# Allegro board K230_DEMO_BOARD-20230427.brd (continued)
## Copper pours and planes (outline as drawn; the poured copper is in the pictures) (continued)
GND on TOP: 58.42,76.2 58.42,73.66 59.44,72.64 59.44,70.36 60.45,69.34 60.45,67.56 60.58,67.44 64.01,67.44 64.39,67.82 64.39,89.53 64.26,89.66 62.48,89.66 62.36,89.53 62.36,76.58 62.23,76.45 58.67,76.45
GND on TOP: 69.98,101.22 69.98,97.66 69.85,97.54 64.9,97.54 64.77,97.66 64.77,101.6 64.9,101.73 66.8,101.73 66.93,101.6 66.93,100.58 66.8,100.46 65.66,100.46 65.53,100.33 65.53,98.68 65.66,98.55 67.56,98.55 67.69,98.68 67.69,99.82 67.82,99.95 68.96,99.95 69.09,100.08 69.09,101.22 69.22,101.35 69.85,101.35
GND on TOP: 71.88,58.29 74.55,58.29 74.68,58.17 74.68,56.26 74.55,56.13 71.88,56.13 71.75,56.26 71.75,58.17
GND on TOP: 65.02,81.03 67.56,81.03 68.07,80.52 69.09,80.52 69.22,80.39 69.22,79.38 69.09,79.25 65.02,79.25 64.9,79.38 64.9,80.9
GND on TOP: outline of 158 points within 12.19,6.73 67.31,41.15 ; 2 cut-outs
GND on TOP: 51.05,93.09 50.93,93.22 50.93,96.01 51.05,96.14 53.85,96.14 53.98,96.27 53.98,98.17 54.48,98.68 54.48,100.84 54.36,100.97 53.72,100.97 53.59,101.09 53.59,101.98 53.72,102.11 56.26,102.11 56.39,101.98 56.39,100.97 56.26,100.84 55.63,100.84 55.5,100.71 55.5,98.42 56.01,97.92 56.01,96.27 56.13,96.14 57.53,96.14 57.66,96.01 57.66,93.47 57.53,93.34 52.32,93.34 52.07,93.09
GND on TOP: 57.03,104.8 56.9,104.92 56.9,112.03 57.03,112.16 64.27,112.16 64.4,112.03 64.4,104.92 64.27,104.8
GND on TOP: 53.47,43.56 53.34,43.69 53.34,45.34 52.96,45.72 52.96,48.77 52.2,49.53 51.56,49.53 51.44,49.66 51.44,50.16 51.31,50.29 49.15,50.29 49.02,50.42 49.02,51.94 49.15,52.07 50.04,52.07 50.16,51.94 50.16,51.44 50.29,51.31 53.34,51.31 53.47,51.44 53.47,62.48 53.59,62.61 54.99,62.61 55.12,62.74 55.12,64.64 55.24,64.77 58.55,64.77 58.67,64.64 58.67,51.31 58.93,51.05 61.98,51.05 62.36,51.44 62.48,51.44 62.61,51.31 62.61,47.24 62.23,46.86 62.23,44.96 60.83,43.56
GND on TOP: 41.15,72.14 42.55,72.14 43.05,71.63 45.21,71.63 45.34,71.5 45.34,68.83 45.09,68.58 43.81,68.58 41.02,71.37 41.02,72.01
GND on TOP: 15.62,53.72 15.49,53.59 12.19,53.59 12.06,53.72 12.06,57.15 12.19,57.28 15.49,57.28 15.62,57.15
GND on TOP: 51.82,78.99 51.82,77.72 51.94,77.6 53.72,77.6 53.85,77.72 53.85,79.76 53.72,79.88 52.32,79.88 52.2,80.01 52.2,81.53 52.07,81.66 50.04,81.66 49.91,81.79 49.91,82.3 50.04,82.42 54.48,82.42 54.74,82.17 54.74,76.96 54.61,76.83 50.16,76.83 50.04,76.96 50.04,78.87 50.29,79.12 51.69,79.12
GND on TOP: 71.88,70.36 74.68,70.36 74.8,70.23 74.8,68.45 74.68,68.33 71.88,68.33 71.75,68.45 71.75,70.23
GND on TOP: 4.32,84.84 4.19,84.96 4.19,87.5 4.32,87.63 5.84,87.63 7.11,86.36 7.11,84.96 6.99,84.84
GND on TOP: 71.88,66.17 74.42,66.17 74.55,66.04 74.55,64.26 74.42,64.14 71.88,64.14 71.75,64.26 71.75,66.04
GND on TOP: 50.93,76.33 52.96,76.33 53.09,76.2 53.09,72.9 52.96,72.77 52.45,72.77 52.32,72.9 52.32,74.68 52.2,74.8 50.93,74.8 50.8,74.93 50.8,76.2
GND on BOTTOM: 20.95,53.34 21.08,53.21 21.08,51.56 20.95,51.44 17.65,51.44 17.27,51.82 17.27,56.39 17.4,56.52 19.43,56.52 19.56,56.39 19.56,53.47 19.68,53.34
GND on BOTTOM: 62.87,13.97 63.25,14.35 67.69,14.35 67.94,14.1 67.94,11.68 67.82,11.56 55.5,11.56 55.24,11.81 55.24,13.84 55.37,13.97
GND on BOTTOM: 46.23,111.38 47.62,111.38 47.75,111.25 47.75,109.86 47.62,109.73 46.23,109.73 46.1,109.86 46.1,111.25
GND on BOTTOM: 73.66,89.28 75.56,89.28 75.69,89.15 75.69,85.98 75.56,85.85 73.66,85.85 73.53,85.98 73.53,89.15
GND on BOTTOM: 38.99,115.57 38.99,116.84 39.12,116.97 41.27,116.97 41.4,116.84 41.4,116.33 41.27,116.2 40.64,116.2 40.51,116.08 40.51,115.57 40.39,115.44 39.12,115.44
GND on BOTTOM: 57.54,111.53 57.67,111.65 63.76,111.65 63.89,111.53 63.89,105.43 63.76,105.3 57.67,105.3 57.54,105.43
GND on BOTTOM: 0.64,103.63 0.64,138 1.03,138.96 2,139.36 39.45,139.36 40.01,138.81 40.01,121.92 39.62,121.54 26.29,121.54 25.65,120.9 25.65,103.5 25.27,103.12 1.14,103.12
GND on GND02: 2,0.64 1.03,1.03 0.64,2 0.64,138 1.03,138.96 2,139.36 58.25,139.36 58.55,139.06 58.55,131.06 47.88,120.4 47.88,108.2 30.61,90.93 30.61,85.34 31.37,84.58 31.37,83.82 30.86,83.31 30.86,82.42 30.99,82.3 31.88,82.3 32.66,83.08 32.66,87.27 33.53,88.14 34.16,88.14 35.81,89.79 35.81,90.55 51.94,106.68 51.94,117.98 56.13,122.17 60.83,122.17 63.25,119.76 63.25,116.33 63.88,115.7 78.8,115.7 79.43,115.06 79.43,2 79.03,1.03 78.07,0.64
GND on ART03: 2,0.64 1.03,1.03 0.64,2 0.64,54.36 2.16,54.36 2.54,53.98 2.54,9.02 8.89,2.67 70.48,2.67 76.45,8.64 76.45,111.76 76.71,112.01 79.18,112.01 79.43,111.76 79.43,2 79.03,1.03 78.07,0.64
GND on ART03: 0.64,64.13 0.64,138 1.03,138.96 2,139.36 57.87,139.36 58.55,138.68 58.55,131.06 58.04,130.56 10.29,130.56 4.19,124.46 4.19,92.08 2.41,90.3 2.41,64.14 2.03,63.75 1.02,63.75
GND on POWER04: 2,0.64 1.03,1.03 0.64,2 0.64,53.47 1.27,54.1 2.03,54.1 3.05,53.09 3.05,13.21 3.93,12.33 3.96,12.25 3.91,12.17 3.8,10.78 5.19,10.9 5.26,10.94 5.34,10.91 7.62,8.64 34.04,8.64 34.29,8.38 34.29,1.14 33.78,0.64
GND on POWER04: 79.43,111.25 79.43,2 79.03,1.03 78.07,0.64 42.16,0.64 41.66,1.14 41.66,7.62 42.16,8.13 69.98,8.13 70.36,8.51 70.36,32.13 75.69,37.47 75.69,85.6 75.95,85.85 75.95,89.41 75.69,89.66 75.69,111.25 75.95,111.51 79.18,111.51
GND on POWER04: 1.14,71.75 0.64,72.26 0.64,78.36 0.64,79.88 0.64,138 1.03,138.96 2,139.36 57.91,139.36 58.42,138.86 58.42,134.61 58.17,134.36 58.17,134.37 5.59,134.37 4.06,132.84 4.06,116.36 1.64,114 4.06,111.64 4.06,78.3 3.53,77.49 4.04,76.65 4.04,75.75 3.53,74.84 4.2,74.05 4.19,74.04 4.19,72.14 3.81,71.75
GND on GND05: 2,0.64 1.03,1.03 0.64,2 0.64,138 1.03,138.96 2,139.36 58.55,139.36 58.55,124.46 63.25,119.76 63.25,116.33 63.88,115.7 78.8,115.7 79.43,115.06 79.43,2 79.03,1.03 78.07,0.64
GND on ART06: 71.88,1.27 71.88,18.92 73.79,20.83 73.79,38.23 72.64,39.37 72.64,44.2 75.06,46.61 75.06,108.84 73.28,110.62 73.28,115.06 73.91,115.7 78.93,115.7 79.43,115.19 79.43,2 79.03,1.03 78.07,0.64 72.52,0.64
GND on ART06: 0.64,86.87 0.64,138 1.03,138.96 2,139.36 25.91,139.36 26.23,139.05 26.23,135.83 6.73,116.33 6.73,104.78 4.95,103 4.95,87.63 4.19,86.87
GND on GND07: 2,0.64 1.03,1.03 0.64,2 0.64,138 1.03,138.96 2,139.36 58.55,139.36 58.55,124.46 63.25,119.76 63.25,116.33 63.88,115.7 78.74,115.7 79.43,115 79.43,2 79.03,1.03 78.07,0.64
GND_SIGNAL on TOP: 64.52,138.18 61.21,138.18 61.09,138.3 61.09,139.19 61.21,139.32 64.52,139.32 64.64,139.19 64.64,138.3
GND_SIGNAL on BOTTOM: 36.2,88.65 36.2,87.25 36.07,87.12 33.78,87.12 33.66,87.25 33.66,89.66 32.26,91.06 31.88,91.06 31.62,90.81 31.62,88.14 32.13,87.63 32.13,87.12 32,87 30.86,87 30.73,87.12 30.73,91.06 31.5,91.82 33.02,91.82
GND_SIGNAL on GND02: 63.88,120.65 61.72,122.81 56.01,122.81 51.44,118.24 51.44,106.81 35.43,90.81 35.43,89.92 34.04,88.52 33.4,88.52 32.51,87.63 32.51,83.19 31.75,82.42 31.11,82.42 30.99,82.55 30.99,83.31 31.5,83.82 31.5,84.84 30.73,85.6 30.73,90.55 48.39,108.2 48.39,120.02 59.56,131.19 59.56,139.11 59.82,139.36 78.07,139.36 79.03,138.96 79.43,138 79.43,116.97 78.93,116.46 64.14,116.46 63.88,116.71
GND_SIGNAL on ART03, POWER04, GND05, ART06, GND07: 63.88,120.65 59.56,124.97 59.56,139.06 59.86,139.36 78.07,139.36 79.03,138.96 79.43,138 79.43,116.97 78.93,116.46 64.14,116.46 63.88,116.71
VBUS on TOP: 73.03,11.18 69.47,11.18 69.22,11.43 69.22,16.26 69.72,16.76 73.15,16.76 73.28,16.64 73.28,16.26 73.15,16.13 71.25,16.13 71.12,16 71.12,11.94 71.25,11.81 73.03,11.81 73.15,11.68 73.15,11.3
VDD_1V8 on TOP: 27.3,30.86 27.43,30.99 28.45,30.99 28.57,30.86 28.57,25.65 28.45,25.53 27.43,25.53 27.3,25.65
VDD_1V8 on TOP: 15.62,47.37 15.62,43.69 15.49,43.56 14.61,43.56 14.48,43.69 14.48,47.37 14.61,47.5 15.49,47.5
VDD_1V8 on TOP: 22.23,29.21 22.35,29.34 22.35,30.73 22.48,30.86 23.24,30.86 23.37,30.73 23.37,25.65 23.24,25.53 22.35,25.53 22.23,25.65
VDD_1V8 on TOP: 15.62,21.84 15.62,17.53 15.49,17.4 14.61,17.4 14.48,17.53 14.48,21.84 14.61,21.97 15.49,21.97
VDD_1V8 on TOP: 23.62,19.81 23.62,16.38 23.5,16.26 19.56,16.26 19.43,16.38 19.43,19.68 19.68,19.94 23.5,19.94
VDD_1V8 on BOTTOM: 46.1,112.27 46.1,114.17 46.23,114.3 47.5,114.3 47.62,114.17 47.62,112.27 47.5,112.14 46.23,112.14
VDD_1V8 on BOTTOM: 25.4,80.01 25.53,79.88 25.53,76.45 25.4,76.33 24.38,76.33 24.26,76.45 24.26,77.09 24.13,77.22 23.11,77.22 22.86,77.47 22.35,77.47 22.23,77.6 22.23,79.88 22.35,80.01
VDD_1V8 on BOTTOM: 30.35,82.42 29.97,82.8 29.59,82.8 29.46,82.93 29.46,85.34 28.83,85.98 28.83,86.49 28.96,86.61 30.23,86.61 30.35,86.49 30.35,83.19 30.73,82.8 30.73,82.55 30.61,82.42
VDD_1V8 on POWER04: 37.34,1.02 36.83,1.52 36.83,9.4 36.07,10.16 9.33,10.16 3.56,15.94 3.56,53.34 1.02,55.88 1.02,70.99 1.14,71.12 5.08,71.12 5.21,71.25 5.21,132.72 5.84,133.35 57.28,133.35 58.55,132.08 58.55,124.46 62.61,120.4 62.61,115.95 74.93,103.63 74.93,37.97 69.47,32.51 69.47,9.53 69.34,9.4 39.88,9.4 39.37,8.89 39.37,1.52 38.86,1.02 ; 1 cut-out
VDD_1V8 on ART06: 24.96,77.41 24.96,79.57 28.45,83.06 30.86,83.06 30.99,82.93 30.99,78.74 31.37,78.36 31.37,77.72 31.24,77.6 26.04,77.6 25.65,77.22 25.15,77.22
VDD_3V3 on TOP: 23.62,6.1 23.5,5.97 19.18,5.97 19.05,6.1 19.05,10.29 19.18,10.41 23.5,10.41 23.62,10.29
VDD_3V3 on TOP: 36.96,31.11 36.96,28.19 37.47,27.69 37.47,25.65 37.34,25.53 35.81,25.53 35.69,25.65 35.69,30.99 35.94,31.24 36.83,31.24
VDD_3V3 on TOP: 59.94,94.36 60.83,95.25 60.83,95.63 60.71,95.76 60.2,95.76 60.07,95.89 58.17,95.89 58.04,95.76 58.04,93.47 58.17,93.34 59.82,93.34 59.94,93.47
VDD_3V3 on TOP: 60.96,99.44 61.09,99.31 61.09,98.04 60.83,97.79 59.69,97.79 59.44,98.04 59.44,99.31 59.56,99.44
VDD_3V3 on TOP: 15.62,34.29 15.62,31.5 15.49,31.37 14.48,31.37 14.48,34.29 14.61,34.42 15.49,34.42
VDD_3V3 on TOP: 50.8,129.16 50.93,129.03 50.93,128.27 50.8,128.14 46.61,128.14 46.48,128.27 46.48,129.03 46.61,129.16
VDD_3V3 on BOTTOM: 40.51,114.68 40.64,114.55 40.64,113.67 40.51,113.54 37.72,113.54 37.59,113.67 37.59,114.55 37.72,114.68
VDD_3V3 on BOTTOM: 70.87,89.28 72.9,89.28 73.03,89.15 73.03,85.98 72.9,85.85 70.87,85.85 70.74,85.98 70.74,89.15
VDD_3V3 on BOTTOM: 33.27,81.15 33.91,81.15 34.29,80.77 35.94,80.77 36.07,80.64 36.07,80.14 35.94,80.01 33.53,80.01 33.15,80.39 33.15,81.03
VDD_3V3 on BOTTOM: 27.69,85.22 27.69,82.55 27.56,82.42 26.92,82.42 26.8,82.55 26.8,85.22 26.92,85.34 27.56,85.34
VDD_3V3 on BOTTOM: 11.43,60.45 11.43,41.27 16.19,36.51 16.19,25.21 16,25.02 6.6,25.02 6.35,25.27 6.35,32.89 3.81,35.43 3.81,55.88 0.76,58.93 0.76,63.37 1.02,63.63 8.26,63.63
VDD_3V3 on ART03: 9.02,3.3 3.17,9.14 3.17,24.38 6.1,27.3 67.06,27.3 69.34,29.59 69.34,83.31 61.59,91.06 32.26,91.06 28.96,87.76 28.96,82.3 28.83,82.17 26.92,82.17 26.8,82.3 26.8,84.2 25.27,85.72 16.51,85.72 11.43,90.81 5.08,90.81 4.95,90.93 4.95,123.57 10.92,129.54 52.2,129.54 62.99,118.75 62.99,115.32 64.52,113.79 74.04,113.79 75.88,111.95 75.88,9.21 69.98,3.3
VDD_5V on TOP: 43.94,31.11 43.94,28.32 43.81,28.19 42.93,28.19 42.8,28.32 42.8,31.11 42.93,31.24 43.81,31.24
VDD_5V on TOP: 43.94,44.58 43.94,43.69 43.81,43.56 42.93,43.56 42.8,43.69 42.8,46.35 42.93,46.48 44.07,46.48 44.2,46.35 44.2,44.83
VDD_5V on TOP: 63.63,44.96 63.63,46.74 63.12,47.24 63.12,51.31 63.25,51.44 63.5,51.44 63.63,51.31 63.63,50.42 63.88,50.16 65.15,50.16 65.28,50.04 65.28,44.96 65.15,44.83 63.75,44.83
VDD_5V on TOP: 46.74,14.22 41.66,19.3 36.83,19.3 36.45,19.68 36.45,20.83 36.96,21.34 39.75,21.34 40.13,20.95 53.34,20.95 53.47,21.08 53.47,23.24 52.96,23.75 52.96,27.81 53.09,27.94 53.34,27.94 53.47,27.81 53.47,26.92 53.72,26.67 58.04,26.67 58.17,26.54 58.17,21.21 58.42,20.95 65.15,20.95 65.41,21.21 65.41,27.05 65.28,27.18 63.88,27.18 63.75,27.3 63.75,28.83 63.88,28.96 69.34,28.96 69.6,28.7 69.6,18.41 67.94,16.76 67.94,14.35 67.82,14.22
VDD_5V on TOP: 50.8,49.28 51.94,49.28 52.45,48.77 52.45,45.97 52.07,45.59 52.07,43.69 51.94,43.56 50.55,43.56 50.42,43.69 50.42,48.9
VDD_5V on TOP: 36.45,10.16 36.45,11.3 36.96,11.81 39.75,11.81 40.13,11.43 42.29,11.43 42.42,11.3 42.42,9.91 42.29,9.78 36.83,9.78
VDD_5V on TOP: 58.8,67.44 58.93,67.56 58.93,72.01 57.66,73.28 57.4,73.28 56.64,72.52 56.64,67.69 56.9,67.44
VDD_5V on BOTTOM: 18.8,35.94 19.3,36.45 44.32,36.45 45.47,37.59 45.47,42.93 43.56,44.83 43.56,48.77 46.35,51.56 53.09,51.56 55.12,53.59 55.12,70.23 56.39,71.5 56.39,80.14 56.64,80.39 60.33,80.39 63.5,77.22 63.5,53.09 65.91,50.67 65.91,30.1 69.98,26.04 69.98,15.11 69.72,14.86 62.99,14.86 62.48,15.37 55.12,15.37 51.88,12.13 45.15,12.13 42.42,9.4 18.92,9.4 18.8,9.53
VDD_5V_O on TOP: 69.47,29.84 69.34,29.72 61.85,29.72 61.72,29.84 61.72,31.5 61.85,31.62 69.34,31.62 69.47,31.5
VDD_5V_O on TOP: 40.39,135.51 40.26,135.64 40.26,137.79 40.39,137.92 42.16,137.92 43.31,136.78 47.5,136.78 47.62,136.65 47.62,135.64 47.5,135.51
VDD_5V_O on TOP: 9.65,90.68 10.54,89.79 10.54,88.77 10.41,88.65 8.76,88.65 8.64,88.77 8.64,90.55 8.76,90.68
VDD_5V_O on BOTTOM: 69.47,51.94 66.04,55.37 66.04,78.74 58.42,86.36 57.28,86.36 57.15,86.23 57.15,84.84 64.26,77.72 64.26,53.21 66.67,50.8 66.67,30.1 66.8,29.97 69.34,29.97 69.47,30.1
VDD_5V_O on ART03: 10.54,90.42 10.73,90.23 10.73,85.28 8.89,83.44 8.89,40.01 13.97,34.92 64.9,34.92 65.02,34.8 65.02,28.45 64.83,28.26 10.86,28.26 2.92,36.2 2.92,90.3 3.05,90.42
VDD_5V_O on ART06: 11.56,90.55 11.56,114.05 31.88,134.37 37.85,134.37 39.12,135.64 42.42,135.64 42.55,135.76 42.55,138.68 42.42,138.81 30.61,138.81 7.24,115.44 7.24,88.9 7.37,88.77 9.78,88.77
VDD_CORE_0V8 on TOP: 41.66,80.39 41.66,78.36 41.53,78.23 40.39,78.23 40.01,78.61 40.01,80.39 40.13,80.52 41.53,80.52
VDD_CORE_0V8 on TOP: 53.72,64.9 53.72,62.99 53.59,62.87 52.96,62.87 52.83,62.74 52.83,61.47 52.7,61.34 51.31,61.34 50.93,61.72 46.35,61.72 46.23,61.85 46.23,64.9 46.35,65.02 53.59,65.02
VDD_CORE_0V8 on POWER04: 30.1,78.11 26.04,78.11 25.78,78.36 25.78,87.76 26.04,88.01 42.8,88.01 58.04,72.77 58.04,60.58 57.66,60.2 48.01,60.2
VDD_CORE_SY on TOP: 47.24,60.33 51.18,60.33 51.82,60.96 52.7,60.96 52.83,60.83 52.83,56.64 52.7,56.52 47.24,56.52 47.12,56.64 47.12,60.2
VDD_CPU_0V8 on TOP: 41.27,73.28 45.21,73.28 45.34,73.15 45.34,72.14 45.21,72.01 44.32,72.01 43.94,72.39 43.18,72.39 42.93,72.64 41.27,72.64 41.15,72.77 41.15,73.15
VDD_CPU_0V8 on TOP: 53.47,37.85 53.34,37.72 53.34,37.21 53.21,37.08 49.28,37.08 49.15,37.21 49.15,38.1 49.28,38.23 50.42,38.23 50.55,38.35 50.55,41.02 50.67,41.15 58.17,41.15 58.29,41.02 58.29,37.97 58.17,37.85
VDD_CPU_0V8 on ART03: 55.37,60.96 59.18,57.15 59.18,36.83 59.05,36.7 43.43,36.7 43.12,37.02 43.12,66.74 35.43,74.42 32.26,74.42 29.34,77.34 29.34,79.76 29.46,79.88 34.29,79.88 34.92,79.25 45.34,79.25 55.37,69.22
VDD_CPU_TI on TOP: 49.15,33.15 49.15,36.58 49.28,36.7 55.24,36.7 55.37,36.58 55.37,33.15 55.24,33.02 49.28,33.02
VDD_IO1V8_SY on TOP: 29.08,21.72 29.21,21.59 29.21,16.89 29.08,16.76 24.89,16.76 24.77,16.89 24.77,21.59 24.89,21.72
VDD_IO3V3_SY on TOP: 29.08,12.19 29.21,12.06 29.21,7.37 29.08,7.24 24.89,7.24 24.77,7.37 24.77,12.06 24.89,12.19
VDD_KPU_0V8 on TOP: 61.72,86.74 61.59,86.61 60.71,86.61 59.82,85.72 58.17,85.72 54.86,89.03 50.55,89.03 50.42,89.15 50.42,92.2 50.55,92.33 51.82,92.33 52.2,91.95 59.05,91.95 61.72,89.28
VDD_KPU_0V8 on TOP: 42.04,85.09 42.04,83.57 41.78,83.31 40.77,83.31 40.64,83.44 40.64,85.09 40.77,85.22 41.91,85.22
VDD_KPU_0V8 on TOP: 64.9,61.72 64.77,61.59 59.56,61.59 59.44,61.72 59.44,65.41 59.56,65.53 64.77,65.53 64.9,65.41
VDD_KPU_0V8 on ART03: 68.45,82.8 68.45,61.21 68.2,60.96 56.64,60.96 56.26,61.34 56.26,69.6 45.59,80.26 29.59,80.26 29.46,80.39 29.46,87.12 32.13,89.79 61.47,89.79
VDD_KPU_TI on TOP: 59.31,56.64 59.31,60.07 59.44,60.2 64.39,60.2 65.66,58.93 65.66,56.64 65.53,56.52 59.44,56.52
DDR_1V8 on TOP: 37.21,39.12 34.29,39.12 34.16,39.24 34.16,42.55 34.29,42.67 37.21,42.67 37.34,42.55 37.34,39.24
DDR_1V8 on BOTTOM: 22.61,53.21 23.11,53.21 23.24,53.09 23.24,46.74 23.11,46.61 19.43,46.61 19.3,46.74 19.3,50.42 19.43,50.55 22.35,50.55 22.48,50.67 22.48,53.09
DDR_1V8 on ART03: 19.3,40.13 19.05,40.39 19.05,51.18 19.18,51.31 21.46,51.31 21.59,51.18 21.59,48.64 23.37,46.86 30.73,46.86 33.66,49.78 33.66,56.13 33.78,56.26 35.94,56.26 37.34,54.86 37.34,40.26 37.21,40.13
DDR_1V8_TI on TOP: 36.96,32.89 36.83,32.77 35.81,32.77 35.69,32.89 35.69,38.35 35.81,38.48 38.23,38.48 38.35,38.35 38.35,37.08 36.96,35.69
DDR_CORE_0V8 on TOP: 16.38,52.45 16.51,52.32 18.67,52.32 18.8,52.45 18.8,57.15 18.67,57.28 16.51,57.28 16.38,57.15
DDR_CORE_0V8 on TOP: 24,67.69 23.88,67.56 21.59,67.56 21.46,67.69 21.46,69.98 21.59,70.1 23.88,70.1 24,69.98
DDR_CORE_0V8 on ART03: 28.96,77.72 28.83,77.6 27.43,77.6 22.48,72.64 22.48,61.09 20.32,58.93 20.32,52.7 20.19,52.58 17.53,52.58 17.4,52.7 17.4,60.58 19.94,63.12 19.94,76.2 22.86,79.12 25.15,79.12 25.78,79.76 28.7,79.76 28.96,79.5
DDR_CORE_TI on TOP: 15.62,49.15 15.49,49.02 14.61,49.02 14.48,49.15 14.48,53.21 14.61,53.34 15.49,53.34 15.62,53.21
DDR_VAA_1V8 on TOP: 37.85,38.99 37.72,39.12 37.72,42.55 37.85,42.67 41.27,42.67 41.4,42.55 41.4,39.12 41.27,38.99
DDR_VAA_1V8 on ART03: 29.21,77.22 28.57,77.22 28.45,77.09 28.45,76.07 28.83,75.69 29.21,75.69 29.59,75.31 29.59,75.06 37.08,67.56 37.08,61.09 37.97,60.2 37.97,40.39 38.1,40.26 42.04,40.26 42.16,40.39 42.16,62.1 40.89,63.37 40.89,67.82 34.8,73.91 32.51,73.91
DDR_VDD2_1V2 on TOP: 34.54,67.56 32.51,67.56 32.38,67.69 32.38,69.22 32.51,69.34 34.54,69.34 34.67,69.22 34.67,67.69
DDR_VDD2_1V2 on TOP: 21.46,40.39 21.46,39.37 21.34,39.24 19.56,39.24 19.43,39.37 19.43,42.55 19.56,42.67 33.15,42.67 33.27,42.55 33.27,40.64 33.15,40.51 21.59,40.51
DDR_VDD2_1V2 on TOP: 18.29,48.26 20.83,48.26 20.95,48.13 20.95,46.74 20.83,46.61 18.29,46.61 18.16,46.74 18.16,48.13
DDR_VDD2_1V2 on BOTTOM: 22.48,55.37 22.86,54.99 22.86,53.59 22.73,53.47 22.35,53.47 22.23,53.59 22.23,53.98 22.1,54.1 20.32,54.1 20.19,54.23 20.19,55.24 20.32,55.37
DDR_VDD2_1V2 on POWER04: 29.97,77.72 30.73,76.96 30.73,76.71 40.13,67.31 40.13,40.39 39.88,40.13 19.68,40.13 17.4,42.42 17.4,71.75 20.89,75.25 24.19,75.25 26.67,77.72
DDR_VDDQ_TI on TOP: 27.43,33.15 27.43,37.08 27.18,37.34 26.42,37.34 26.29,37.47 26.29,38.86 26.42,38.99 28.45,38.99 28.57,38.86 28.57,33.15 28.45,33.02 27.56,33.02
FTVCC_1V8 on BOTTOM: 67.31,112.14 67.31,110.24 67.18,110.11 66.17,110.11 66.04,110.24 66.04,111.19 62.99,114.24 56.9,114.24 55.37,112.71 55.37,103.25 55.63,103 64.39,103 64.52,102.87 64.52,101.09 64.26,100.84 55.12,100.84 52.83,103.12 52.83,106.3 53.21,106.68 53.21,113.79 55.5,116.08 63.37,116.08
FTVCC_3V3 on TOP: 58.29,100.2 58.17,100.33 58.17,101.85 58.29,101.98 60.58,101.98 60.71,101.85 60.71,100.33 60.58,100.2
FTVCC_3V3 on ART06: 56.32,114.62 54.86,113.16 54.86,107.19 55.56,106.49 55.56,102.81 60.2,98.17 68.96,98.17 69.22,98.42 69.22,112.78 67.37,114.62
MIPI_0V8 on TOP: 17.27,26.67 16.51,26.67 16.38,26.8 16.38,29.46 17.65,30.73 17.65,38.73 17.78,38.86 18.8,38.86 18.92,38.73 18.92,30.23 17.4,28.7 17.4,26.8
MIPI_0V8 on ART03: 19.05,81.79 12.19,74.93 12.19,63.12 12.26,63.06 12.26,43.37 16.51,39.12 18.54,39.12 18.8,38.86 18.8,35.69 18.67,35.56 14.73,35.56 9.78,40.51 9.78,79.12 15.75,85.09 25.4,85.09 26.16,84.33 26.16,81.92 26.04,81.79
MIPI_0V8_TI on TOP: 15.62,23.62 15.49,23.5 14.61,23.5 14.48,23.62 14.48,27.56 14.61,27.69 15.49,27.69 15.62,27.56
MIPI_1V8 on TOP: 16.51,39.12 16.38,39.24 16.38,44.07 16.51,44.2 18.8,44.2 18.92,44.07 18.92,39.24 18.8,39.12
MIPI_1V8 on ART03: 25.78,80.26 25.02,79.5 22.73,79.5 19.56,76.33 19.56,63.63 16.76,60.83 16.76,51.69 17.53,50.93 17.53,41.4 17.27,41.15 15.11,41.15 12.95,43.31 12.95,60.58 17.27,64.9 17.27,67.31 15.88,68.71 15.88,76.58 20.83,81.53 25.65,81.53 25.78,81.41
MIPI_1V8_TI on TOP: 15.62,36.07 15.49,35.94 14.61,35.94 14.48,36.07 14.48,40.01 14.61,40.13 15.49,40.13 15.62,40.01
RTC_1V8 on TOP: 44.83,35.94 45.85,35.94 46.1,36.2 46.1,40.64 45.97,40.77 42.8,40.77 42.67,40.64 42.67,38.99 44.58,37.08 44.58,36.2
RTC_1V8 on BOTTOM: 48.01,74.55 47.62,74.93 44.32,74.93 42.29,76.96 31.62,76.96 31.5,77.09 31.5,77.72 32.26,78.49 34.67,78.49 35.05,78.11 49.15,78.11 50.16,77.09 50.16,72.77 51.05,71.88 51.05,57.4 42.93,49.28 42.93,44.58 44.83,42.67 44.83,39.24 44.7,39.12 42.8,39.12 42.67,39.24 42.67,41.15 40.39,43.43 40.39,50.8 42.1,52.51 42.16,52.51 48.01,58.36
RTC_1V8_TI on TOP: 43.94,32.89 43.81,32.77 42.93,32.77 42.8,32.89 42.8,36.96 42.93,37.08 43.81,37.08 43.94,36.96
U_3V3 on TOP: 55.88,99.31 57.4,99.31 57.53,99.44 59.05,99.44 59.18,99.31 59.18,98.17 57.66,96.65 56.9,96.65 56.77,96.77 56.77,98.3 56.64,98.42 55.88,98.42 55.75,98.55 55.75,99.19
U_5V on TOP: 73.15,101.47 70.36,101.47 70.23,101.6 70.23,102.23 70.36,102.36 71.25,102.36 71.63,101.98 73.15,101.98 73.28,101.85 73.28,101.6
U_5V on TOP: 51.94,96.65 53.09,96.65 53.21,96.77 53.21,98.42 53.47,98.68 54.1,98.68 54.23,98.81 54.23,99.19 54.1,99.31 53.59,99.31 53.47,99.44 53.47,99.95 53.59,100.08 54.1,100.08 54.23,100.2 54.23,100.58 54.1,100.71 52.58,100.71 51.82,99.95 51.82,96.77
U_5V on TOP: 71.25,106.93 73.03,106.93 73.15,106.81 73.15,106.43 73.03,106.3 70.36,106.3 70.23,106.43 70.23,107.06 70.36,107.19 70.99,107.19
U_5V on BOTTOM: 52.58,99.95 54.23,99.95 54.36,99.82 54.36,98.3 54.74,97.92 57.02,97.92 59.44,100.33 66.67,100.33 69.09,102.74 69.09,106.93 69.34,107.19 70.74,107.19 70.99,106.93 70.99,97.41 70.87,97.28 59.69,97.28 58.55,96.14 53.34,96.14 52.45,97.03 52.45,99.82
USB0_OTG_VBUS on TOP: 71.88,76.07 73.79,76.07 75.31,74.55 75.31,72.14 73.66,70.48 70.87,70.48 70.74,70.61 70.74,70.99 70.87,71.12 73.28,71.12 74.68,72.52 74.68,74.17 73.41,75.44 71.88,75.44 71.75,75.56 71.75,75.95
USB1_OTG_VBUS on TOP: 73.15,59.18 73.28,59.05 73.28,58.55 73.15,58.42 70.87,58.42 70.74,58.55 70.74,59.05 70.87,59.18
USB1_OTG_VBUS on TOP: 73.15,64.01 73.28,63.88 73.28,63.5 73.15,63.37 71.63,63.37 71.5,63.25 70.74,63.25 70.61,63.37 70.61,63.88 70.74,64.01
N21033005 on TOP: 21.72,33.27 21.72,38.86 21.84,38.99 24.51,38.99 24.64,38.86 24.64,37.47 24.51,37.34 22.99,37.34 22.86,37.21 22.86,33.27 22.73,33.15 21.84,33.15
N21034668 on BOTTOM: 35.94,82.42 36.07,82.3 36.07,81.41 35.94,81.28 34.04,81.28 33.91,81.41 33.15,81.41 32.89,81.15 32.38,81.15 32.26,81.28 32.26,81.53 32.64,81.92 32.64,82.3 32.77,82.42
N21116429 on TOP: 30.61,17.65 30.48,17.78 30.48,21.97 30.61,22.1 33.27,22.1 33.4,21.97 33.4,19.81 32.64,19.05 32.64,17.78 32.51,17.65
N21117469 on TOP: 48.77,55.12 48.9,55.24 52.96,55.24 53.09,55.12 53.09,52.45 52.96,52.32 50.93,52.32 50.16,53.09 48.9,53.09 48.77,53.21
N21118160 on TOP: 30.61,8.13 30.48,8.26 30.48,12.06 30.61,12.19 33.27,12.19 33.4,12.06 33.4,10.29 32.64,9.53 32.64,8.26 32.51,8.13
N21119930 on TOP: 43.94,48.13 43.81,48.01 42.93,48.01 42.8,48.13 42.8,52.07 42.93,52.2 43.81,52.2 43.94,52.07
N21125022 on TOP: 62.48,95.76 63.12,95.76 64.26,94.61 64.26,92.08 64.14,91.95 63.5,91.95 63.37,92.08 63.37,94.23 62.36,95.25 62.36,95.63
N21268003 on TOP: 65.79,52.83 65.53,52.58 63.88,52.58 62.99,51.69 62.74,51.69 61.85,52.58 61.47,52.58 61.34,52.7 61.34,55.12 61.47,55.24 65.66,55.24 65.79,55.12
N21270973 on TOP: 60.45,84.45 60.58,84.58 60.58,86.11 60.71,86.23 61.59,86.23 61.72,86.11 61.72,80.77 61.59,80.64 57.4,80.64 57.28,80.77 57.28,84.33 57.4,84.45
N21271057 on TOP: 57.4,79.25 57.53,79.38 61.72,79.38 61.85,79.25 61.85,77.09 61.72,76.96 58.67,76.96 58.19,76.48 58.19,73.63 58.14,73.58 57.94,73.58 57.89,73.63 57.89,77.09 57.4,77.57
N21272325 on TOP: 53.85,29.21 52.83,28.19 52.58,28.19 51.56,29.21 51.31,29.21 51.18,29.34 51.18,31.62 51.31,31.75 55.24,31.75 55.37,31.62 55.37,29.34 55.24,29.21

Small or netless copper shapes (teardrops, artwork), in the pictures only: 39 on TOP

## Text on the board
Ref Des/Silkscreen Bottom: USB0_OTG_EN | USB1_OTG_EN | GND | VDD_1V8 | VDD_3V3 | GPIO26 | GPIO28 | GPIO30 | GPIO33 | GPIO34 | GPIO35 | GPIO36 | GPIO37 | GPIO27 | GPIO29 | GPIO32 | GPIO31 | GPIO52 | GPIO53 | UART3_RXD | UART3_TXD | VDD_5V_O | SYS_SW | PW_EN | OUT0 | INT5 | INT4 | RTC_1V8 | INT3 | INT2 | INT1 | INT0 | SYS_ON_OFF
Ref Des/Silkscreen Top: 1V8 | GND | 3V3 | DDR_CORE_0V8 | 0V8 | DDR_1V8 | PLL_0V8 | RTC_1V8 | ADC0--5 | AVDD_1V8 | KPU_0V8 | VDD5V_O | 5V | UART0/3 | USB0 | USB1 | TCK | TDO | TDI | TMS | RST | NC | MIPI_1V8 | DDR_1V2 | DDR_VAA_1V8 | CORE_0V8 | CPU_0V8 | RESET | K230 DEMO BOARD | DC 5V | : | OFF | ON
User.23: FIGURE | SIZE | 8.0 | 10.0 | 40.0 | 45.0 | 55.0 | 115.0 | 125.0 | 24.0 | 28.0 | 48.0 | 60.0 | 50.0x30.0 | 70.0x30.0 | 70.0x40.0 | DRILL CHART: TOP to BOTTOM | ALL UNITS ARE IN MILS | PLATED | NON-PLATED | QTY | 597 | 1136 | 98 | 2 | 4 | 6 | 8
